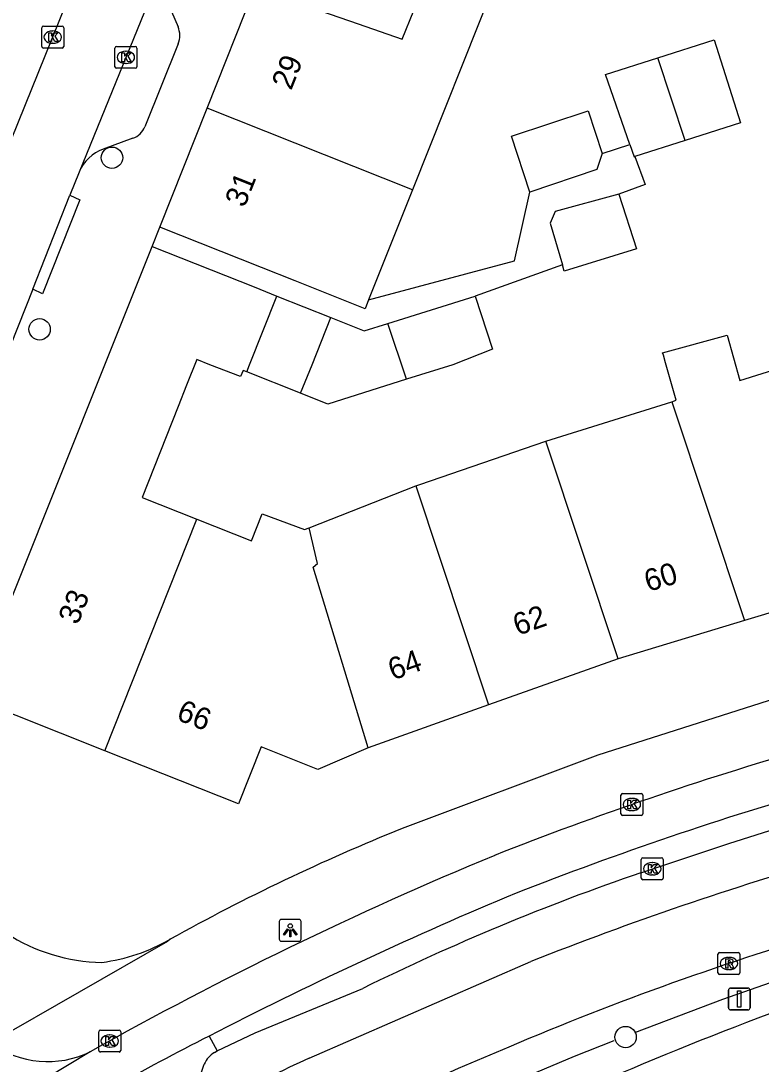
# Model space of a CAD drawing. Extents: x 161801 to 162379, y 382315 to 382832.
# Drawn here: x 162153.34 to 162187.15, y 382468.07 to 382515.69 of the extents above; entities that cross this region are included whole.
import ezdxf

# ---------------------------------------------------------------- set-up
doc = ezdxf.new("R2010")
doc.units = 0
for name, color, linetype in [('IMGEO_Berm_open', 7, 'Continuous'), ('IMGEO_Boom', 7, 'Continuous'), ('IMGEO_Fietspad_gesloten', 7, 'Continuous'), ('IMGEO_Fietspad_open', 7, 'Continuous'), ('IMGEO_Hek', 7, 'Continuous'), ('IMGEO_Kolk', 7, 'Continuous'), ('IMGEO_Lichtpunt', 7, 'Continuous'), ('IMGEO_Pand', 7, 'Continuous'), ('IMGEO_Pand_nummerreeks', 7, 'Continuous'), ('IMGEO_Parkeervlak_open', 7, 'Continuous'), ('IMGEO_Rijbaan_lokaal_gesloten', 7, 'Continuous'), ('IMGEO_Rijbaan_lokaal_open', 7, 'Continuous'), ('IMGEO_Rioolput', 7, 'Continuous'), ('IMGEO_Verkeersbordpaal', 7, 'Continuous'), ('IMGEO_Voetpad_open', 7, 'Continuous')]:
    doc.layers.add(name, color=color, linetype=linetype)

msp = doc.modelspace()

# ---------------------------------------------------------------- linework, layer by layer
at = {"layer": 'IMGEO_Berm_open'}
msp.add_lwpolyline([(162161.932, 382469.351), (162162.307, 382468.677)], dxfattribs=at)
at = {"layer": 'IMGEO_Boom'}
for centre in [(162157.498, 382509.446), (162154.192, 382501.615), (162180.956, 382469.306)]:
    msp.add_circle(centre, 0.489, dxfattribs=at)
at = {"layer": 'IMGEO_Fietspad_gesloten'}
msp.add_lwpolyline([(162156.503, 382468.637), (162148.661, 382463.917)], dxfattribs=at)
msp.add_arc((162154.56, 382472.598), 4.412, 233.84, 296.1281, dxfattribs=at)
at = {"layer": 'IMGEO_Fietspad_open'}
for centre, radius, start, end in [((162233.268, 382329.842), 158.842, 106.11816, 111.52979), ((162233.268, 382330.005), 156.723, 106.14456, 111.62285), ((162242.395, 382315.148), 175.887, 112.53867, 119.23117), ((162253.052, 382292.072), 199.326, 112.89185, 117.20288), ((162254.989, 382288.479), 203.407, 117.22553, 118.64693)]:
    msp.add_arc(centre, radius, start, end, dxfattribs=at)
at = {"layer": 'IMGEO_Hek'}
for points in [[(162181.377, 382469.508), (162185.392, 382471.037), (162189.448, 382472.454), (162193.541, 382473.757), (162194.518, 382474.049)], [(162165.207, 382461.984), (162168.482, 382463.757), (162171.812, 382465.424), (162175.195, 382466.983), (162178.626, 382468.432), (162180.436, 382469.145)]]:
    msp.add_lwpolyline(points, dxfattribs=at)
at = {"layer": 'IMGEO_Kolk'}
for p, q in [((162154.291, 382514.526), (162154.291, 382515.378)), ((162154.366, 382515.452), (162155.218, 382515.452)), ((162154.779, 382515.232), (162154.804, 382515.232)), ((162155.292, 382515.378), (162155.292, 382514.526)), ((162154.802, 382514.672), (162154.777, 382514.672)), ((162155.218, 382514.452), (162154.366, 382514.452)), ((162157.632, 382513.603), (162157.632, 382514.455)), ((162157.707, 382514.529), (162158.559, 382514.529)), ((162158.12, 382514.309), (162158.145, 382514.309)), ((162158.633, 382514.455), (162158.633, 382513.603)), ((162158.143, 382513.749), (162158.118, 382513.749)), ((162158.559, 382513.529), (162157.707, 382513.529)), ((162180.741, 382479.497), (162180.741, 382480.349)), ((162180.816, 382480.423), (162181.668, 382480.423)), ((162181.742, 382480.349), (162181.742, 382479.497)), ((162181.229, 382480.203), (162181.254, 382480.203)), ((162181.668, 382479.423), (162180.816, 382479.423)), ((162181.252, 382479.643), (162181.227, 382479.643)), ((162181.748, 382477.488), (162182.6, 382477.488)), ((162181.673, 382476.562), (162181.673, 382477.414)), ((162182.161, 382477.268), (162182.186, 382477.268)), ((162182.674, 382477.414), (162182.674, 382476.562)), ((162182.6, 382476.488), (162181.748, 382476.488)), ((162182.184, 382476.708), (162182.159, 382476.708)), ((162156.894, 382468.698), (162156.894, 382469.55)), ((162156.969, 382469.624), (162157.821, 382469.624)), ((162157.382, 382469.404), (162157.407, 382469.404)), ((162157.895, 382469.55), (162157.895, 382468.698)), ((162157.821, 382468.624), (162156.969, 382468.624)), ((162157.405, 382468.844), (162157.38, 382468.844))]:
    msp.add_line(p, q, dxfattribs=at)
for points in [[(162154.291, 382514.526), (162154.291, 382515.378)], [(162154.366, 382515.452), (162155.218, 382515.452)], [(162154.612, 382515.152), (162154.735, 382515.152), (162154.735, 382515.001), (162154.865, 382515.152), (162155.029, 382515.152), (162154.883, 382515.001), (162155.036, 382514.752), (162154.884, 382514.752), (162154.799, 382514.916), (162154.735, 382514.849), (162154.735, 382514.752), (162154.612, 382514.752), (162154.612, 382515.152)], [(162155.292, 382515.378), (162155.292, 382514.526)], [(162155.218, 382514.452), (162154.366, 382514.452)], [(162157.632, 382513.603), (162157.632, 382514.455)], [(162157.707, 382514.529), (162158.559, 382514.529)], [(162157.953, 382514.229), (162158.076, 382514.229), (162158.076, 382514.078), (162158.206, 382514.229), (162158.37, 382514.229), (162158.224, 382514.078), (162158.377, 382513.829), (162158.225, 382513.829), (162158.14, 382513.993), (162158.076, 382513.926), (162158.076, 382513.829), (162157.953, 382513.829), (162157.953, 382514.229)], [(162158.633, 382514.455), (162158.633, 382513.603)], [(162158.559, 382513.529), (162157.707, 382513.529)], [(162180.741, 382479.497), (162180.741, 382480.349)], [(162180.816, 382480.423), (162181.668, 382480.423)], [(162181.742, 382480.349), (162181.742, 382479.497)], [(162181.062, 382480.123), (162181.185, 382480.123), (162181.185, 382479.972), (162181.315, 382480.123), (162181.479, 382480.123), (162181.333, 382479.972), (162181.486, 382479.723), (162181.334, 382479.723), (162181.249, 382479.887), (162181.185, 382479.82), (162181.185, 382479.723), (162181.062, 382479.723), (162181.062, 382480.123)], [(162181.668, 382479.423), (162180.816, 382479.423)], [(162181.748, 382477.488), (162182.6, 382477.488)], [(162181.673, 382476.562), (162181.673, 382477.414)], [(162181.994, 382477.188), (162182.117, 382477.188), (162182.117, 382477.037), (162182.247, 382477.188), (162182.411, 382477.188), (162182.265, 382477.037), (162182.418, 382476.788), (162182.266, 382476.788), (162182.181, 382476.952), (162182.117, 382476.885), (162182.117, 382476.788), (162181.994, 382476.788), (162181.994, 382477.188)], [(162182.674, 382477.414), (162182.674, 382476.562)], [(162182.6, 382476.488), (162181.748, 382476.488)], [(162156.894, 382468.698), (162156.894, 382469.55)], [(162156.969, 382469.624), (162157.821, 382469.624)], [(162157.895, 382469.55), (162157.895, 382468.698)], [(162157.215, 382469.324), (162157.338, 382469.324), (162157.338, 382469.173), (162157.468, 382469.324), (162157.632, 382469.324), (162157.486, 382469.173), (162157.639, 382468.924), (162157.487, 382468.924), (162157.402, 382469.088), (162157.338, 382469.021), (162157.338, 382468.924), (162157.215, 382468.924), (162157.215, 382469.324)], [(162157.821, 382468.624), (162156.969, 382468.624)]]:
    msp.add_lwpolyline(points, dxfattribs=at)
for centre, start, end in [((162154.368, 382515.376), 91.552, 178.448), ((162154.368, 382515.376), 91.552, 178.448), ((162155.216, 382515.376), 1.552, 88.448), ((162155.216, 382515.376), 1.552, 88.448), ((162154.368, 382514.528), 181.552, 268.448), ((162154.368, 382514.528), 181.552, 268.448), ((162155.216, 382514.528), 271.552, 358.448), ((162155.216, 382514.528), 271.552, 358.448), ((162157.709, 382514.453), 91.552, 178.448), ((162157.709, 382514.453), 91.552, 178.448), ((162158.557, 382514.453), 1.552, 88.448), ((162158.557, 382514.453), 1.552, 88.448), ((162157.709, 382513.605), 181.552, 268.448), ((162157.709, 382513.605), 181.552, 268.448), ((162158.557, 382513.605), 271.552, 358.448), ((162158.557, 382513.605), 271.552, 358.448), ((162180.818, 382480.347), 91.552, 178.448), ((162180.818, 382480.347), 91.552, 178.448), ((162181.666, 382480.347), 1.552, 88.448), ((162181.666, 382480.347), 1.552, 88.448), ((162180.818, 382479.499), 181.552, 268.448), ((162180.818, 382479.499), 181.552, 268.448), ((162181.666, 382479.499), 271.552, 358.448), ((162181.666, 382479.499), 271.552, 358.448), ((162181.75, 382477.412), 91.552, 178.448), ((162181.75, 382477.412), 91.552, 178.448), ((162182.598, 382477.412), 1.552, 88.448), ((162182.598, 382477.412), 1.552, 88.448), ((162181.75, 382476.564), 181.552, 268.448), ((162181.75, 382476.564), 181.552, 268.448), ((162182.598, 382476.564), 271.552, 358.448), ((162182.598, 382476.564), 271.552, 358.448), ((162156.971, 382469.548), 91.552, 178.448), ((162156.971, 382469.548), 91.552, 178.448), ((162157.819, 382469.548), 1.552, 88.448), ((162157.819, 382469.548), 1.552, 88.448), ((162156.971, 382468.7), 181.552, 268.448), ((162156.971, 382468.7), 181.552, 268.448), ((162157.819, 382468.7), 271.552, 358.448), ((162157.819, 382468.7), 271.552, 358.448)]:
    msp.add_arc(centre, 0.0765, start, end, dxfattribs=at)
for centre, major_axis, ratio, start_param, end_param in [((162154.778, 382514.952), (-0.387, 0.002), 0.722429, 4.712389, 7.853982), ((162154.803, 382514.952), (-0.39, 0.002), 0.717154, 1.570796, 4.712389), ((162158.119, 382514.029), (-0.387, 0.002), 0.722429, 4.712389, 7.853982), ((162158.144, 382514.029), (-0.39, 0.002), 0.717154, 1.570796, 4.712389), ((162181.228, 382479.923), (-0.387, 0.002), 0.722429, 4.712389, 7.853982), ((162181.253, 382479.923), (-0.39, 0.002), 0.717154, 1.570796, 4.712389), ((162182.16, 382476.988), (-0.387, 0.002), 0.722429, 4.712389, 7.853982), ((162182.185, 382476.988), (-0.39, 0.002), 0.717154, 1.570796, 4.712389), ((162157.381, 382469.124), (-0.387, 0.002), 0.722429, 4.712389, 7.853982), ((162157.406, 382469.124), (-0.39, 0.002), 0.717154, 1.570796, 4.712389)]:
    msp.add_ellipse(centre, major_axis=major_axis, ratio=ratio, start_param=start_param, end_param=end_param, dxfattribs=at)
at = {"layer": 'IMGEO_Lichtpunt'}
for p, q in [((162165.14, 382474.582), (162165.14, 382473.775)), ((162165.14, 382474.582), (162165.14, 382473.775)), ((162166.042, 382474.677), (162165.234, 382474.677)), ((162166.042, 382474.677), (162165.234, 382474.677)), ((162166.136, 382473.775), (162166.136, 382474.582)), ((162166.136, 382473.775), (162166.136, 382474.582)), ((162165.234, 382473.681), (162166.042, 382473.681)), ((162165.234, 382473.681), (162166.042, 382473.681))]:
    msp.add_line(p, q, dxfattribs=at)
for points in [[(162165.514, 382474.246), (162165.553, 382474.218), (162165.365, 382473.956), (162165.327, 382473.983), (162165.514, 382474.246)], [(162165.616, 382474.198), (162165.663, 382474.198), (162165.663, 382473.876), (162165.616, 382473.876), (162165.616, 382474.198)], [(162165.726, 382474.218), (162165.764, 382474.245), (162165.951, 382473.983), (162165.912, 382473.955), (162165.726, 382474.218)]]:
    msp.add_lwpolyline(points, dxfattribs=at)
msp.add_circle((162165.639, 382474.38), 0.0994, dxfattribs=at)
for centre, start, end in [((162165.234, 382474.582), 90, 180), ((162165.234, 382474.582), 90, 180), ((162166.042, 382474.582), 0, 90), ((162166.042, 382474.582), 0, 90), ((162165.234, 382473.775), 180, 270), ((162165.234, 382473.775), 180, 270), ((162166.042, 382473.775), 270, 0), ((162166.042, 382473.775), 270, 360)]:
    msp.add_arc(centre, 0.0946, start, end, dxfattribs=at)
at = {"layer": 'IMGEO_Pand'}
for points in [[(162161.842, 382511.712), (162164.027, 382517.204)], [(162164.027, 382517.204), (162168.749, 382515.558), (162170.758, 382514.857), (162171.278, 382516.165), (162174.976, 382517.436), (162171.217, 382507.985)], [(162182.426, 382514.006), (162184.998, 382514.826), (162186.204, 382511.043), (162183.68, 382510.239)], [(162181.153, 382510.048), (162180.039, 382513.245), (162182.426, 382514.006)], [(162183.68, 382510.239), (162182.426, 382514.006)], [(162159.68, 382506.277), (162161.842, 382511.712)], [(162171.217, 382507.985), (162161.842, 382511.712)], [(162176.578, 382507.877), (162175.739, 382510.434), (162179.25, 382511.587), (162179.888, 382509.646)], [(162181.153, 382510.048), (162181.346, 382509.494), (162181.384, 382509.506)], [(162183.68, 382510.239), (162181.384, 382509.506)], [(162179.888, 382509.646), (162179.644, 382508.914), (162176.578, 382507.877)], [(162171.217, 382507.985), (162169.22, 382502.966)], [(162180.641, 382507.782), (162177.745, 382506.996), (162177.517, 382506.465), (162178.07, 382504.55)], [(162180.641, 382507.782), (162181.447, 382505.283), (162178.152, 382504.266), (162178.07, 382504.55)], [(162169.22, 382502.966), (162169.054, 382502.548), (162165.857, 382503.82), (162164.326, 382504.429), (162159.68, 382506.277)], [(162151.084, 382484.795), (162157.179, 382500), (162159.341, 382505.394)], [(162159.341, 382505.394), (162163.987, 382503.546), (162165.029, 382503.131)], [(162163.65, 382499.669), (162163.782, 382500), (162165.029, 382503.131)], [(162165.029, 382503.131), (162167.492, 382502.151)], [(162170.099, 382501.882), (162174.082, 382503.133)], [(162174.082, 382503.133), (162174.87, 382500.7), (162173.063, 382500), (162170.948, 382499.334)], [(162166.112, 382498.692), (162166.634, 382500), (162167.492, 382502.151)], [(162167.492, 382502.151), (162169.021, 382501.543), (162170.099, 382501.882)], [(162170.948, 382499.334), (162170.099, 382501.882)], [(162183.06, 382498.309), (162183.265, 382498.373), (162182.779, 382500.084), (162182.68, 382500.432), (162182.648, 382500.547), (162185.587, 382501.343), (162186.171, 382499.284), (162188.454, 382500), (162189.318, 382500.271), (162189.399, 382500), (162189.593, 382499.683)], [(162163.65, 382499.669), (162163.486, 382499.734), (162163.375, 382499.454), (162161.974, 382500), (162161.371, 382500.235), (162160.904, 382499.059), (162160.522, 382498.096), (162158.871, 382493.937), (162161.368, 382492.946)], [(162166.112, 382498.692), (162163.65, 382499.669)], [(162170.948, 382499.334), (162167.35, 382498.201), (162166.112, 382498.692)], [(162177.308, 382496.505), (162183.06, 382498.309)], [(162183.06, 382498.309), (162186.388, 382488.315)], [(162171.37, 382494.466), (162171.552, 382494.537), (162177.308, 382496.505)], [(162180.615, 382486.576), (162177.308, 382496.505)], [(162166.501, 382492.558), (162171.37, 382494.466)], [(162171.37, 382494.466), (162174.7, 382484.467)], [(162161.368, 382492.946), (162163.865, 382491.956), (162164.356, 382493.191), (162166.288, 382492.474), (162166.501, 382492.558)], [(162157.175, 382482.378), (162161.368, 382492.946)], [(162169.206, 382482.506), (162166.689, 382490.753), (162166.885, 382490.925), (162166.501, 382492.558)], [(162192.314, 382490.1), (162186.388, 382488.315)], [(162186.388, 382488.315), (162180.615, 382486.576)], [(162180.615, 382486.576), (162174.7, 382484.467)], [(162157.175, 382482.378), (162151.084, 382484.795)], [(162174.7, 382484.467), (162169.206, 382482.506)], [(162169.206, 382482.506), (162166.903, 382481.527), (162164.315, 382482.554), (162163.283, 382479.954), (162157.175, 382482.378)]]:
    msp.add_lwpolyline(points, dxfattribs=at)
at = {"layer": 'IMGEO_Parkeervlak_open'}
for points in [[(162181.656, 382476.81), (162185.663, 382478.139), (162190.041, 382479.519)], [(162162.307, 382468.677), (162164.037, 382469.502), (162168.949, 382471.527)], [(162162.18, 382468.602), (162162.307, 382468.677)], [(162161.142, 382466.35), (162161.714, 382468.07)]]:
    msp.add_lwpolyline(points, dxfattribs=at)
for centre, radius, start, end in [((162217.249, 382373.277), 109.48, 108.97197, 116.17872), ((162162.722, 382467.657), 1.089, 119.8322, 157.735)]:
    msp.add_arc(centre, radius, start, end, dxfattribs=at)
at = {"layer": 'IMGEO_Rijbaan_lokaal_gesloten'}
msp.add_lwpolyline([(162166.505, 382468.342), (162176.626, 382472.748)], dxfattribs=at)
for centre, radius, start, end in [((162230.29, 382337.919), 145.116, 105.90174, 111.70337), ((162228.65, 382344.283), 135.383, 106.25552, 113.06268), ((162242.027, 382324.056), 156.127, 107.11411, 113.74549), ((162233.969, 382328.707), 151.802, 112.60681, 120.16205), ((162208.951, 382375.898), 101.723, 114.66266, 119.26965)]:
    msp.add_arc(centre, radius, start, end, dxfattribs=at)
at = {"layer": 'IMGEO_Rijbaan_lokaal_open'}
for points in [[(162139.739, 382477.746), (162156.661, 382519.576)], [(162159.816, 382518.171), (162155.996, 382508.79)], [(162155.996, 382508.79), (162155.577, 382507.733)], [(162153.876, 382503.445), (162155.577, 382507.733)], [(162153.876, 382503.445), (162152.509, 382500), (162152.397, 382499.706), (162152.355, 382499.601)]]:
    msp.add_lwpolyline(points, dxfattribs=at)
at = {"layer": 'IMGEO_Rioolput'}
for p, q in [((162185.249, 382473.163), (162186.101, 382473.163)), ((162185.174, 382472.237), (162185.174, 382473.089)), ((162185.662, 382472.943), (162185.687, 382472.943)), ((162186.175, 382473.089), (162186.175, 382472.237)), ((162185.685, 382472.383), (162185.66, 382472.383)), ((162186.101, 382472.163), (162185.249, 382472.163))]:
    msp.add_line(p, q, dxfattribs=at)
for points in [[(162185.249, 382473.163), (162186.101, 382473.163)], [(162185.174, 382472.237), (162185.174, 382473.089)], [(162185.763, 382472.861), (162185.511, 382472.863), (162185.511, 382472.463)], [(162185.689, 382472.782), (162185.635, 382472.782), (162185.635, 382472.701)], [(162185.635, 382472.701), (162185.687, 382472.701)], [(162186.175, 382473.089), (162186.175, 382472.237)], [(162185.511, 382472.463), (162185.635, 382472.463), (162185.635, 382472.625), (162185.646, 382472.625)], [(162185.693, 382472.596), (162185.764, 382472.463), (162185.904, 382472.463), (162185.839, 382472.589)], [(162186.101, 382472.163), (162185.249, 382472.163)]]:
    msp.add_lwpolyline(points, dxfattribs=at)
for centre, radius, start, end in [((162185.251, 382473.087), 0.0765, 91.552, 178.448), ((162185.251, 382473.087), 0.0765, 91.552, 178.448), ((162186.099, 382473.087), 0.0765, 1.552, 88.448), ((162186.099, 382473.087), 0.0765, 1.552, 88.448), ((162185.671, 382472.89), 0.19, 274.7715, 282.9687), ((162185.695, 382472.686), 0.0964, 77.0061, 93.1865), ((162185.709, 382472.743), 0.0378, 276.6634, 79.6772), ((162185.762, 382472.751), 0.109, 350.3612, 89.416), ((162185.76, 382472.751), 0.112, 277.5842, 350.9817), ((162185.251, 382472.239), 0.0765, 181.552, 268.448), ((162185.251, 382472.239), 0.0765, 181.552, 268.448), ((162185.645, 382472.572), 0.0533, 26.0293, 88.6989), ((162185.744, 382472.536), 0.108, 29.5134, 73.7905), ((162186.099, 382472.239), 0.0765, 271.552, 358.448), ((162186.099, 382472.239), 0.0765, 271.552, 358.448)]:
    msp.add_arc(centre, radius, start, end, dxfattribs=at)
for centre, major_axis, ratio, start_param, end_param in [((162185.661, 382472.663), (-0.387, 0.002), 0.722429, 4.712389, 7.853982), ((162185.686, 382472.663), (-0.39, 0.002), 0.717154, 1.570796, 4.712389)]:
    msp.add_ellipse(centre, major_axis=major_axis, ratio=ratio, start_param=start_param, end_param=end_param, dxfattribs=at)
at = {"layer": 'IMGEO_Verkeersbordpaal'}
for p, q in [((162185.649, 382470.644), (162185.649, 382471.444)), ((162185.649, 382471.444), (162185.649, 382470.644)), ((162185.749, 382471.544), (162186.539, 382471.544)), ((162186.539, 382471.544), (162185.749, 382471.544)), ((162186.639, 382471.444), (162186.639, 382470.644)), ((162186.639, 382470.644), (162186.639, 382471.444)), ((162186.539, 382470.544), (162185.749, 382470.544)), ((162185.749, 382470.544), (162186.539, 382470.544))]:
    msp.add_line(p, q, dxfattribs=at)
msp.add_lwpolyline([(162186.069, 382471.419), (162186.219, 382471.419), (162186.219, 382470.669), (162186.069, 382470.669), (162186.069, 382471.419)], dxfattribs=at)
for centre, start, end in [((162185.749, 382471.444), 90, 180), ((162185.749, 382471.444), 90, 180), ((162186.539, 382471.444), 0, 90), ((162186.539, 382471.444), 360, 90), ((162185.749, 382470.644), 180, 270), ((162185.749, 382470.644), 180, 270), ((162186.539, 382470.644), 270, 0), ((162186.539, 382470.644), 270, 0)]:
    msp.add_arc(centre, 0.1, start, end, dxfattribs=at)
at = {"layer": 'IMGEO_Voetpad_open'}
for points in [[(162159.905, 382516.835), (162160.514, 382515.422)], [(162160.523, 382514.649), (162158.999, 382510.856)], [(162158.458, 382510.332), (162157.099, 382509.839)], [(162179.888, 382509.646), (162181.153, 382510.048)], [(162181.384, 382509.506), (162181.851, 382508.221), (162180.641, 382507.782)], [(162155.577, 382507.733), (162156.036, 382507.527), (162154.32, 382503.238), (162153.876, 382503.445)], [(162169.22, 382502.966), (162175.88, 382504.742), (162176.578, 382507.877)], [(162265.144, 382506.94), (162262.221, 382506.045), (162240.584, 382500), (162187.464, 382484.653), (162179.692, 382482.178), (162170.756, 382478.827)], [(162159.341, 382505.394), (162159.68, 382506.277)], [(162178.07, 382504.55), (162174.082, 382503.133)], [(162160.15, 382473.769), (162160.034, 382473.662), (162151.957, 382469.036)]]:
    msp.add_lwpolyline(points, dxfattribs=at)
for centre, radius, start, end in [((162159.593, 382515.025), 1.003, 337.9915, 23.3426), ((162158.142, 382511.2), 0.923, 290.0186, 338.1524), ((162157.747, 382508.054), 1.899, 109.9401, 157.1851), ((162206.322, 382390.6), 95.126, 111.95553, 119.03741), ((162157.161, 382480.952), 8.238, 237.0018, 269.14), ((162155.958, 382481.025), 8.38, 277.3962, 300.0139)]:
    msp.add_arc(centre, radius, start, end, dxfattribs=at)

# ---------------------------------------------------------------- texts
at = {"layer": 'IMGEO_Pand_nummerreeks'}
for s, rotation, p in [('29', 68.3063, (162165.683, 382512.491)), ('31', 68.308, (162163.551, 382507.133)), ('60', 16.7606, (162181.986, 382489.621)), ('33', 68.1591, (162155.936, 382488.083)), ('62', 19.6266, (162176.029, 382487.617)), ('64', 19.6443, (162170.327, 382485.582)), ('66', 338.355, (162160.391, 382483.812))]:
    msp.add_text(s, height=1, rotation=rotation, dxfattribs=at).set_placement(p)

doc.saveas('drawing.dxf')
